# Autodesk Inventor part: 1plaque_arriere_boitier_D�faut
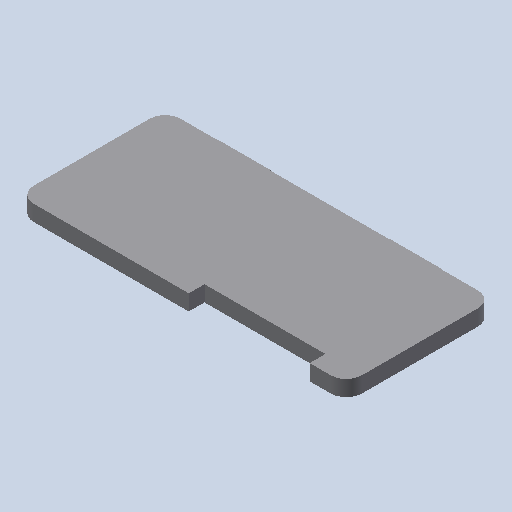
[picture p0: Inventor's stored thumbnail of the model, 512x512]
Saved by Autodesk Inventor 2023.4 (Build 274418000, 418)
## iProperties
Created: 2011-01
Part Number: 1plaque_arriere_boitier_D�faut
Document SubType Name: Modeling
Designer: eric
Density: 1 g/cm^3
Mass: 5.02583 g
Surface Area: 38.973 cm^2
Volume: 5.02583 cm^3
Material: Générique
Appearance: Par défaut
Author: eric
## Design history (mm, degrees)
feature "Base1"
node "Corps solides"
node "Corps surfaciques"
node "Solide1"
